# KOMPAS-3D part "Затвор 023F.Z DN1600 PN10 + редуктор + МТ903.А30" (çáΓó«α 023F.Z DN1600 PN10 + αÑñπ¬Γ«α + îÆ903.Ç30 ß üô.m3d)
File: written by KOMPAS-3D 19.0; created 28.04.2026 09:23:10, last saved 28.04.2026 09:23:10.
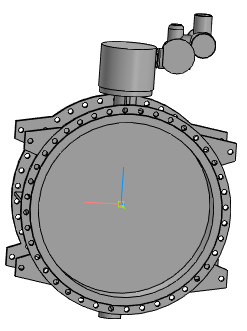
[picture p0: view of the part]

Document properties: Автор: Энергия; Полное имя файла: ..\Затвор 023F.Z DN1600 PN10 + редуктор + МТ903.А30.a3d

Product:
- Part/product: Затвор 023F.Z DN1600 PN10 + редуктор + МТ903.А30
    Масса: 4510.88

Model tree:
1. Операция без истории:1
